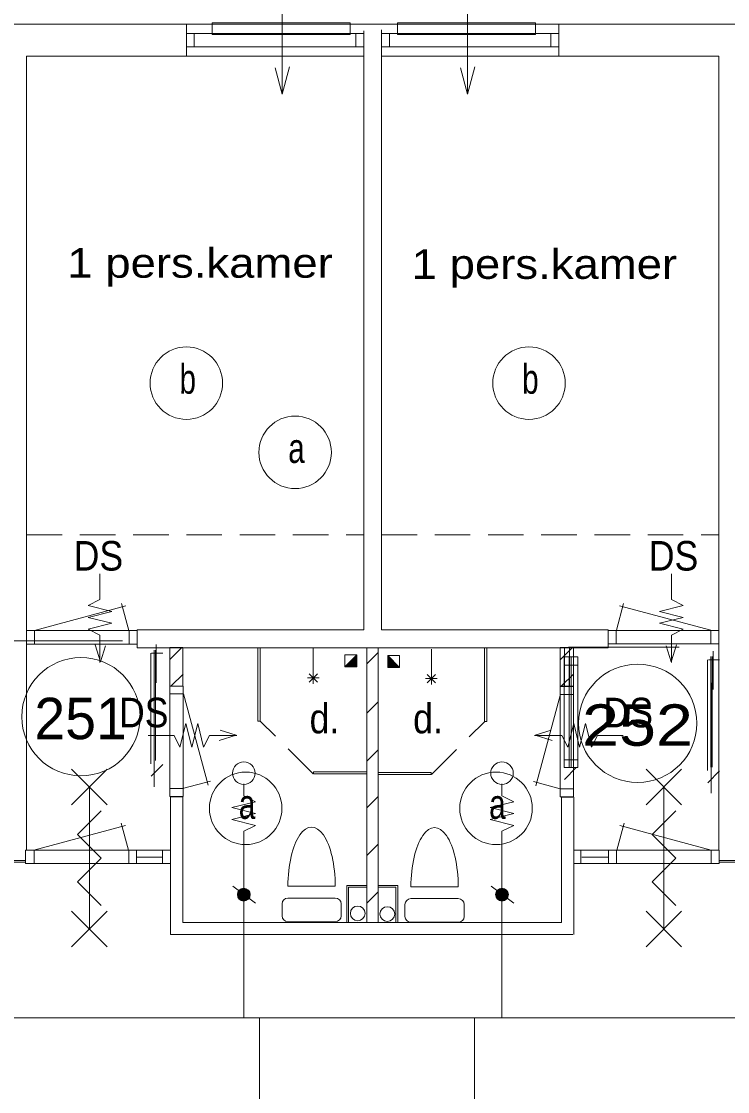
# Model space of a CAD drawing. Extents: x 295824 to 414724, y 24924 to 109024.
# Drawn here: x 308047 to 314015, y 95396 to 104442 of the extents above; entities that cross this region are included whole.
import ezdxf
from ezdxf.enums import TextEntityAlignment as Align

# ---------------------------------------------------------------- set-up
doc = ezdxf.new("R2010")
doc.units = 0
doc.header["$LTSCALE"] = 100
doc.linetypes.add('MEDIUM_DASHED', pattern=[4.5, 3, -1.5])
for name, color, linetype, lineweight in [('1', 7, 'Continuous', 13), ('16', 7, 'Continuous', 13), ('24', 7, 'Continuous', 13), ('61', 7, 'Continuous', 13)]:
    doc.layers.add(name, color=color, linetype=linetype, lineweight=lineweight)

msp = doc.modelspace()

# ---------------------------------------------------------------- hatches: boundary and pattern name
at = {"layer": '24'}
for points in [[(309981, 97060.5, 1), (309872.4, 97060.5, 1)], [(312162.9, 97060.5, 1), (312054.3, 97060.5, 1)]]:
    msp.add_hatch(color=256, dxfattribs=at).paths.add_polyline_path(points)
at = {"layer": '61'}
for points in [[(310781.4, 98986.3), (310881.4, 99086.3), (310881.4, 98986.3)], [(311243.8, 98980.9), (311143.8, 99080.9), (311143.8, 98980.9)]]:
    msp.add_hatch(color=256, dxfattribs=at).paths.add_polyline_path(points)

# ---------------------------------------------------------------- linework, layer by layer
at = {"layer": '1'}
for p, q in [((309926.7, 97029.2), (309926.7, 96018.7)), ((312108.6, 97022.5), (312108.6, 96018.7)), ((310059.9, 95135.8), (310059.9, 96018.7)), ((311875.5, 95130.8), (311875.5, 96018.7))]:
    msp.add_line(p, q, dxfattribs=at)
at = {"layer": '16'}
for p, q in [((308610.8, 99404.1), (308810.8, 99454.1)), ((313641.1, 99404.1), (313441.1, 99454.1)), ((309487.2, 98305.9), (309437.2, 98505.9)), ((312764.7, 98305.9), (312814.7, 98505.9))]:
    msp.add_line(p, q, dxfattribs=at)
at = {"layer": '24'}
for p, q in [((310251.5, 103826.9), (310191.9, 104049.3)), ((311817.2, 103826.9), (311757.6, 104049.3)), ((308714.2, 99028.7), (308669.1, 99172.8)), ((308756.6, 99164.5), (308714.2, 99028.7)), ((313495.3, 99164.5), (313537.7, 99028.7)), ((313537.7, 99028.7), (313582.7, 99172.8)), ((309726.8, 98451.7), (309862.6, 98409.3)), ((312525.1, 98451.7), (312389.2, 98409.3)), ((309862.6, 98409.3), (309718.4, 98364.2)), ((312389.2, 98409.3), (312533.4, 98364.2)), ((309926.7, 97545.9), (309926.7, 97006.4)), ((312108.6, 97545.9), (312108.6, 97037.5)), ((309835, 97131.3), (310026.6, 96989.6)), ((312017, 97131.3), (312208.6, 96989.6)), ((304113.6, 96018.7), (328710.3, 96018.7))]:
    msp.add_line(p, q, dxfattribs=at)
for points in [[(310251.5, 104801.9), (310251.5, 103826.9), (310313.2, 104057.1)], [(311817.2, 104801.9), (311817.2, 103826.9), (311878.8, 104057.1)], [(308810.8, 99454.1), (308610.8, 99504.1), (308710.8, 99554.1), (308710.8, 99772.8)], [(313441.1, 99454.1), (313641.1, 99504.1), (313541.1, 99554.1), (313541.1, 99772.8)], [(308710.8, 99022.8), (308710.8, 99254.1), (308610.8, 99304.1), (308810.8, 99354.1), (308610.8, 99404.1)], [(313541.1, 99022.8), (313541.1, 99254.1), (313641.1, 99304.1), (313441.1, 99354.1), (313641.1, 99404.1)], [(309437.2, 98505.9), (309387.2, 98305.9), (309337.2, 98405.9), (309118.5, 98405.9)], [(309868.4, 98405.9), (309637.2, 98405.9), (309587.2, 98305.9), (309537.2, 98505.9), (309487.2, 98305.9)], [(312383.4, 98405.9), (312614.7, 98405.9), (312664.7, 98305.9), (312714.7, 98505.9), (312764.7, 98305.9)], [(312814.7, 98505.9), (312864.7, 98305.9), (312914.7, 98405.9), (313133.4, 98405.9)], [(309926.7, 97995.9), (309926.7, 97895.9), (310026.7, 97845.9), (309826.7, 97795.9), (310026.7, 97745.9), (309826.7, 97695.9), (310026.7, 97645.9), (309926.7, 97595.9), (309926.7, 97545.9)], [(312108.6, 97995.9), (312108.6, 97895.9), (312208.6, 97845.9), (312008.6, 97795.9), (312208.6, 97745.9), (312008.6, 97695.9), (312208.6, 97645.9), (312108.6, 97595.9), (312108.6, 97545.9)]]:
    msp.add_lwpolyline(points, dxfattribs=at)
for points in [[(309660.2, 104331), (310826.1, 104331), (310826.1, 104431), (309660.2, 104431)], [(311225.9, 104331), (312391.8, 104331), (312391.8, 104431), (311225.9, 104431)]]:
    msp.add_lwpolyline(points, close=True, dxfattribs=at)
for centre, radius in [((309926.7, 98087.5), 95), ((312108.6, 98087.5), 95), ((309926.7, 97060.5), 54.3), ((312108.6, 97060.5), 54.3)]:
    msp.add_circle(centre, radius, dxfattribs=at)
at = {"layer": '61'}
for p, q in [((309441.5, 104147.6), (309441.5, 104417.6)), ((312589.8, 104147.6), (312589.8, 104416.9)), ((309508.3, 104225.9), (309508.3, 104339.8)), ((310873.3, 104225.3), (310873.3, 104339.3)), ((311156.8, 104226.2), (311156.8, 104340.2)), ((312521.1, 104225.9), (312521.1, 104339.6)), ((308090.1, 104147.6), (310940.1, 104147.6)), ((308090.1, 97436.7), (308090.1, 104147.6)), ((313940.1, 104147.6), (311090.1, 104147.6)), ((313940.1, 97436.7), (313940.1, 104147.6)), ((308955, 99294.3), (308894.2, 99521.1)), ((313075.3, 99295.4), (313136.1, 99522.2)), ((308156.5, 99293.7), (308929.3, 99500.7)), ((313873.7, 99294.8), (313101, 99501.8)), ((308157.3, 99179), (308157.3, 99293)), ((308957.3, 99179), (308957.3, 99293)), ((309024.3, 99179), (309024.3, 99293)), ((313005.2, 99297.6), (313005.2, 99147.6)), ((313006, 99180.1), (313006, 99294.1)), ((313073, 99180.1), (313073, 99294.1)), ((313873, 99180.1), (313873, 99294.1)), ((308900.2, 99206.9), (307966.2, 99206.9)), ((309186.9, 98850.8), (309186.9, 99174.9)), ((309301.2, 99048), (309400.9, 99147.7)), ((309302.7, 98824.2), (309302.7, 99148.3)), ((309302.7, 99148.3), (309412.6, 99148.3)), ((309412.6, 98824.2), (309412.6, 99148.3)), ((310063.9, 99148.6), (310063.9, 98528.1)), ((310965.8, 99148.9), (310965.8, 96823.9)), ((311062.1, 99148.9), (311062.1, 96823.9)), ((312601.6, 98824.2), (312601.6, 99148.3)), ((312601.6, 99148.3), (312711.6, 99148.3)), ((312603.3, 99048), (312703, 99147.7)), ((312636.6, 98823), (312636.6, 99147)), ((313605.4, 99151.2), (312671.4, 99151.2)), ((312679.3, 98823), (312679.3, 99147)), ((312711.6, 98824.2), (312711.6, 99148.3)), ((309139.9, 98166.6), (309139.9, 99100.6)), ((309242.1, 99101.4), (309147.4, 99101.4)), ((309168.7, 98194.5), (309168.7, 99128.5)), ((309179.7, 98194.5), (309179.7, 99128.5)), ((310513.8, 98942.1), (310513.8, 99142.1)), ((310966.3, 99012.7), (311062.1, 99108.5)), ((311511.5, 98936.8), (311511.5, 99136.8)), ((311961.3, 99143.2), (311961.3, 98522.8)), ((312743.2, 99072.1), (312638, 99072.1)), ((312676.7, 98136.1), (312676.7, 99068.5)), ((312692.5, 98136.1), (312692.5, 99068.5)), ((312749.2, 98136.1), (312749.2, 99068.5)), ((313873.8, 98138.8), (313873.8, 99072.8)), ((313884.9, 98138.8), (313884.9, 99072.8)), ((313892, 98795.1), (313892, 99119.2)), ((312749.2, 99001.5), (312635.2, 99001.5)), ((313845, 98110.9), (313845, 99044.9)), ((313947.3, 99045.7), (313852.5, 99045.7)), ((309170.2, 98905.7), (309170.2, 97973.3)), ((309313.5, 98825.4), (309413.2, 98925.1)), ((310563.8, 98892.1), (310463.8, 98892.1)), ((310549.1, 98927.4), (310478.4, 98856.7)), ((310549.1, 98856.7), (310478.4, 98927.4)), ((310513.8, 98942.1), (310513.8, 98842.1)), ((311461.5, 98886.8), (311561.5, 98886.8)), ((311476.1, 98922.1), (311546.8, 98851.4)), ((311476.1, 98851.4), (311546.8, 98922.1)), ((311511.5, 98936.8), (311511.5, 98836.8)), ((312611.9, 98825.4), (312711.6, 98925.1)), ((309300.9, 98823.3), (309300.9, 97890.9)), ((309302.7, 98824.2), (309412.6, 98824.2)), ((312600.9, 98820.7), (312714.9, 98820.7)), ((312601.6, 98824.2), (312711.6, 98824.2)), ((312714.3, 98820.7), (312714.3, 97886.7)), ((313875.3, 98850), (313875.3, 97917.6)), ((309300.9, 98757.9), (309414.9, 98757.9)), ((309418, 98758.7), (309625.1, 97985.9)), ((312602.3, 98754.4), (312395.2, 97981.7)), ((312714.3, 98753.7), (312600.3, 98753.7)), ((310966.3, 98594.6), (311062.1, 98690.4)), ((310966.3, 98190), (311062.1, 98285.8)), ((309242.3, 98161.9), (309142.6, 98062.2)), ((312749.2, 98201.5), (312635.2, 98201.5)), ((308771.2, 98119.9), (308471.2, 97819.9)), ((308471.2, 98119.9), (308771.2, 97819.9)), ((310963.9, 98098.6), (310514.8, 98098.6)), ((310514.8, 98080.6), (310514.8, 98098.6)), ((310964.3, 98080.6), (310514.8, 98080.6)), ((311061, 98075.2), (311510.4, 98075.2)), ((311061.3, 98093.2), (311510.4, 98093.2)), ((311510.4, 98075.2), (311510.4, 98093.2)), ((312736.6, 98134), (312636.9, 98034.3)), ((312747.4, 98135.2), (312637.4, 98135.2)), ((313627, 98119.9), (313327, 97819.9)), ((313327, 98119.9), (313627, 97819.9)), ((313947.4, 98106.1), (313847.7, 98006.4)), ((308621.2, 96769.9), (308621.2, 97969.9)), ((309418.7, 97960.3), (309645.5, 98021)), ((312601.6, 97956), (312374.8, 98016.8)), ((313477, 96769.9), (313477, 97969.9)), ((309300.9, 97957.9), (309414.9, 97957.9)), ((309306.8, 97887.3), (309306.8, 97321.5)), ((309306.8, 97887.3), (309412.1, 97887.3)), ((310966.3, 97794), (311062.1, 97889.8)), ((312714.3, 97953.7), (312600.3, 97953.7)), ((312612.1, 97885.9), (312612.1, 96823.9)), ((312612.1, 97885.9), (312706.8, 97885.9)), ((312716.7, 97885.9), (312716.7, 97423.9)), ((308153.2, 97437.3), (308925.9, 97644.4)), ((308951.6, 97437.9), (308890.8, 97664.8)), ((313078.9, 97437.9), (313139.7, 97664.8)), ((313877.3, 97437.3), (313104.6, 97644.4)), ((308153.9, 97322.7), (308153.9, 97436.7)), ((308953.9, 97322.7), (308953.9, 97436.7)), ((309020.9, 97322.7), (309020.9, 97436.7)), ((309238.6, 97323.9), (309238.6, 97437.9)), ((310966.3, 97390.7), (311062.1, 97486.4)), ((312775.3, 97323.9), (312775.3, 97437.9)), ((313009.6, 97322.7), (313009.6, 97436.7)), ((313076.6, 97322.7), (313076.6, 97436.7)), ((313876.6, 97322.7), (313876.6, 97436.7)), ((307944.7, 97348.9), (308085.9, 97348.9)), ((309238.6, 97376.8), (309020.9, 97376.8)), ((312783.6, 97376.8), (313009.6, 97376.8)), ((313944.8, 97348.9), (314086, 97348.9)), ((307944.7, 97333.9), (308085.9, 97333.9)), ((312715.1, 96722.6), (312715.1, 97322.6)), ((313944.8, 97333.9), (314086, 97333.9)), ((310699.5, 97131.8), (310299.5, 97131.8)), ((310812, 97124.3), (310962, 97124.3)), ((310812, 96824.3), (310812, 97124.3)), ((310966.3, 96989.8), (311062.1, 97085.5)), ((311062.1, 97123.9), (311212.1, 97123.9)), ((311212.1, 97123.9), (311212.1, 96823.9)), ((311738.9, 97126.8), (311338.9, 97126.8)), ((310249.5, 96881.8), (310249.5, 96981.8)), ((310299.5, 97031.8), (310699.5, 97031.8)), ((310749.5, 96981.8), (310749.5, 96881.8)), ((311288.9, 96876.8), (311288.9, 96976.8)), ((311338.9, 97026.8), (311738.9, 97026.8)), ((311788.9, 96976.8), (311788.9, 96876.8)), ((308771.2, 96919.9), (308471.2, 96619.9)), ((308471.2, 96919.9), (308771.2, 96619.9)), ((313627, 96919.9), (313327, 96619.9)), ((313327, 96919.9), (313627, 96619.9)), ((310699.5, 96831.8), (310299.5, 96831.8)), ((311738.9, 96826.8), (311338.9, 96826.8))]:
    msp.add_line(p, q, dxfattribs=at)
at = {"layer": '61', "linetype": 'MEDIUM_DASHED'}
for p, q in [((308091.8, 100101), (310940.1, 100101)), ((311090.6, 100101), (313940.8, 100101)), ((310512.7, 98081), (310065.8, 98527.9)), ((311512.5, 98075.7), (311959.4, 98522.6))]:
    msp.add_line(p, q, dxfattribs=at)
at = {"layer": '61'}
for points in [[(301796.6, 92184.5), (301820.1, 104417.6), (332210.1, 104417.6)], [(310940.1, 104361.7), (310940.1, 99297.6), (309025.1, 99297.6), (309025.1, 99147.6), (313005.2, 99147.6)], [(311090.1, 104370.5), (311090.1, 99297.6), (313005.2, 99297.6)], [(308090.3, 99179), (308090.3, 99293), (309024.3, 99293)], [(309024.3, 99179), (308090.3, 99179), (308090.3, 99293)], [(313940, 99180.1), (313940, 99294.1), (313006, 99294.1)], [(313006, 99180.1), (313940, 99180.1), (313940, 99294.1)], [(310045.9, 99148.6), (310045.9, 98528.1), (310063.9, 98528.1)], [(310881.4, 99086.3), (310881.4, 98986.3), (310781.4, 98986.3)], [(311143.8, 99080.9), (311143.8, 98980.9), (311243.8, 98980.9)], [(311979.3, 99143.2), (311979.3, 98522.8), (311961.3, 98522.8)], [(309412.1, 97887.3), (309412.1, 96823.9), (312612.1, 96823.9)], [(308721.2, 96969.9), (308521.2, 97169.9), (308721.2, 97369.9), (308521.2, 97569.9), (308721.2, 97769.9)], [(313577, 96969.9), (313377, 97169.9), (313577, 97369.9), (313377, 97569.9), (313577, 97769.9)], [(309306.8, 97323.9), (309306.8, 96723.9), (312706.8, 96723.9)], [(310797, 96824.3), (310797, 97139.3), (310962, 97139.3)], [(311062.1, 97138.9), (311227.1, 97138.9), (311227.1, 96823.9)]]:
    msp.add_lwpolyline(points, dxfattribs=at)
for points in [[(309441.5, 104225.8), (309441.5, 104339.8), (310940.1, 104339.8), (310940.1, 104225.8)], [(311090.5, 104225.9), (311090.5, 104339.9), (312589.8, 104339.9), (312589.8, 104225.9)], [(310881.4, 99086.3), (310781.4, 99086.3), (310781.4, 98986.3)], [(310781.4, 98986.3), (310881.4, 99086.3), (310881.4, 98986.3)], [(311143.8, 99080.9), (311243.8, 99080.9), (311243.8, 98980.9)], [(311243.8, 98980.9), (311143.8, 99080.9), (311143.8, 98980.9)], [(312749.2, 99069.4), (312635.2, 99069.4), (312635.2, 98135.4), (312749.2, 98135.4)], [(309300.9, 97890), (309414.9, 97890), (309414.9, 98824), (309300.9, 98824)], [(312714.3, 98820.7), (312714.3, 97886.7), (312600.3, 97886.7), (312600.3, 98820.7)], [(308080.8, 97322.7), (308080.8, 97436.7), (309307.2, 97436.7), (309307.2, 97322.7)], [(312716.6, 97322.7), (312716.6, 97436.7), (313943.6, 97436.7), (313943.6, 97322.7)]]:
    msp.add_lwpolyline(points, close=True, dxfattribs=at)
for centre, radius in [((309441.3, 101384.2), 306.3), ((312336.8, 101384.2), 306.3), ((310360.1, 100799.1), 306.3), ((308550.2, 98564.7), 500), ((313255.3, 98509), 500), ((309942.5, 97790.1), 306.3), ((312058.4, 97790.1), 306.3), ((310889.6, 96901.8), 62.5), ((311139.6, 96896.3), 62.5)]:
    msp.add_circle(centre, radius, dxfattribs=at)
for centre, start, end in [((310299.5, 96981.8), 90, 180), ((310699.5, 96981.8), 0, 90), ((311338.9, 96976.8), 90, 180), ((311738.9, 96976.8), 0, 90), ((310299.5, 96881.8), 180, 270), ((310699.5, 96881.8), 270, 0), ((311338.9, 96876.8), 180, 270), ((311738.9, 96876.8), 270, 0)]:
    msp.add_arc(centre, 50, start, end, dxfattribs=at)
for centre in [(310499.5, 97131.8), (311538.9, 97126.8)]:
    msp.add_ellipse(centre, major_axis=(0, 500), ratio=0.4, start_param=4.712389, end_param=7.853982, dxfattribs=at)

# ---------------------------------------------------------------- texts
at = {"layer": '24', "width": 0.9}
for p in [(308488.9, 99799.9), (313349.5, 99799.9), (308872, 98474.9), (312966.5, 98474.9)]:
    msp.add_text('DS', height=250, dxfattribs=at).set_placement(p)
at = {"layer": '61'}
for s, width, p in [('1 pers.kamer', 1.15, (308435.4, 102275.4)), ('1 pers.kamer', 1.15, (311345.3, 102265.6)), ('b', 0.75, (309383.3, 101295)), ('b', 0.75, (312278.8, 101295)), ('a', 0.75, (310302.1, 100709.9)), ('d.', 0.9, (310482.7, 98424.3)), ('d.', 0.9, (311357.6, 98424.3)), ('a', 0.75, (309884.5, 97700.9)), ('a', 0.75, (312000.4, 97700.9))]:
    msp.add_text(s, height=250, dxfattribs=dict(at, width=width)).set_placement(p)
msp.add_text('251', height=350, dxfattribs=at).set_placement((308547.3, 98374.8), align=Align.CENTER)
at = {"layer": '61', "width": 1.2}
msp.add_text('252', height=350, dxfattribs=at).set_placement((313253.8, 98319.1), align=Align.CENTER)

doc.saveas('drawing.dxf')
